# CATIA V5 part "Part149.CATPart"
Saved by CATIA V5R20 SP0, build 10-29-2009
Part number: FA 084700-2 comprimido
Revision: ANY
Definition: UNKNOWN
Nomenclature: FA 084700-2 comprimido
Source: Unknown
Bounding box of the stored display mesh (mm): x -2.45 to 2.45, y 0 to 4.72, z -2.45 to 2.45
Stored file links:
  C:\Users\Utente\Desktop\IO LAVORO\3D X SITO CF\CUMSA\3D files FA\FA 105706-20\Part149.CATPart

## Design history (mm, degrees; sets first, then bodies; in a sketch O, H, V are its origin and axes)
Body1 "Cortar-Extruir1" (main body)
  Solid1: solid without history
